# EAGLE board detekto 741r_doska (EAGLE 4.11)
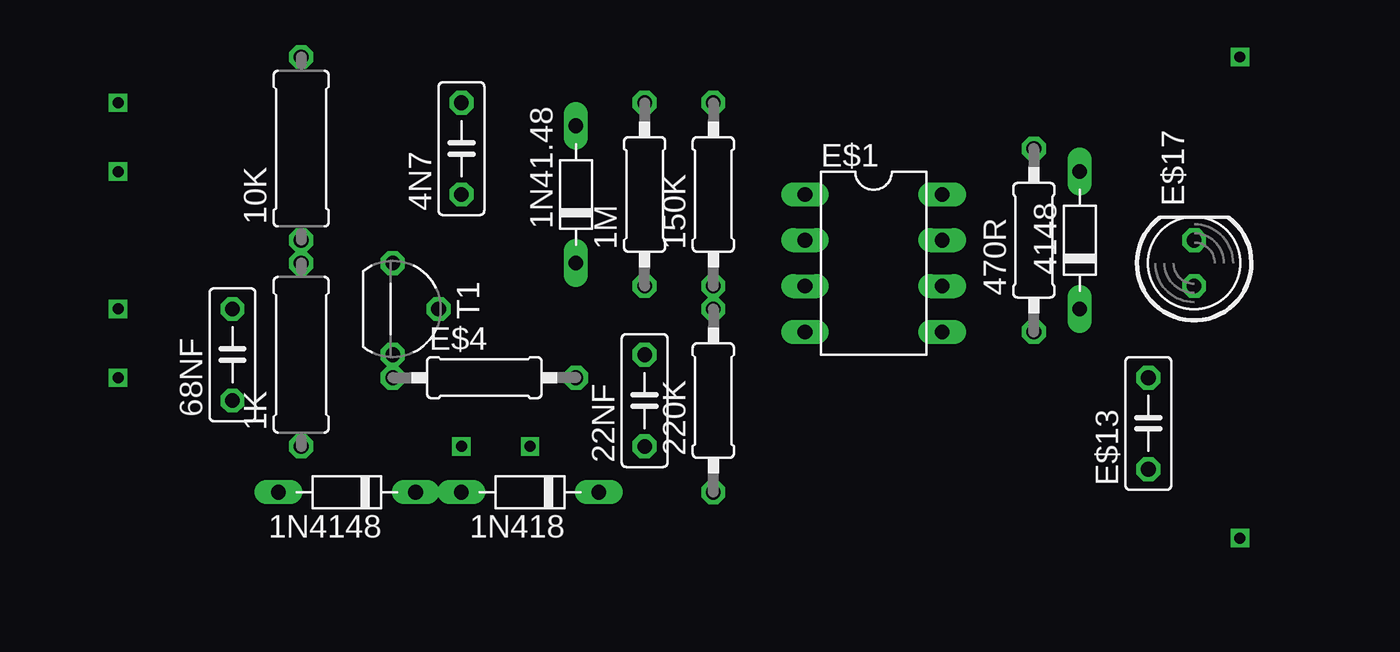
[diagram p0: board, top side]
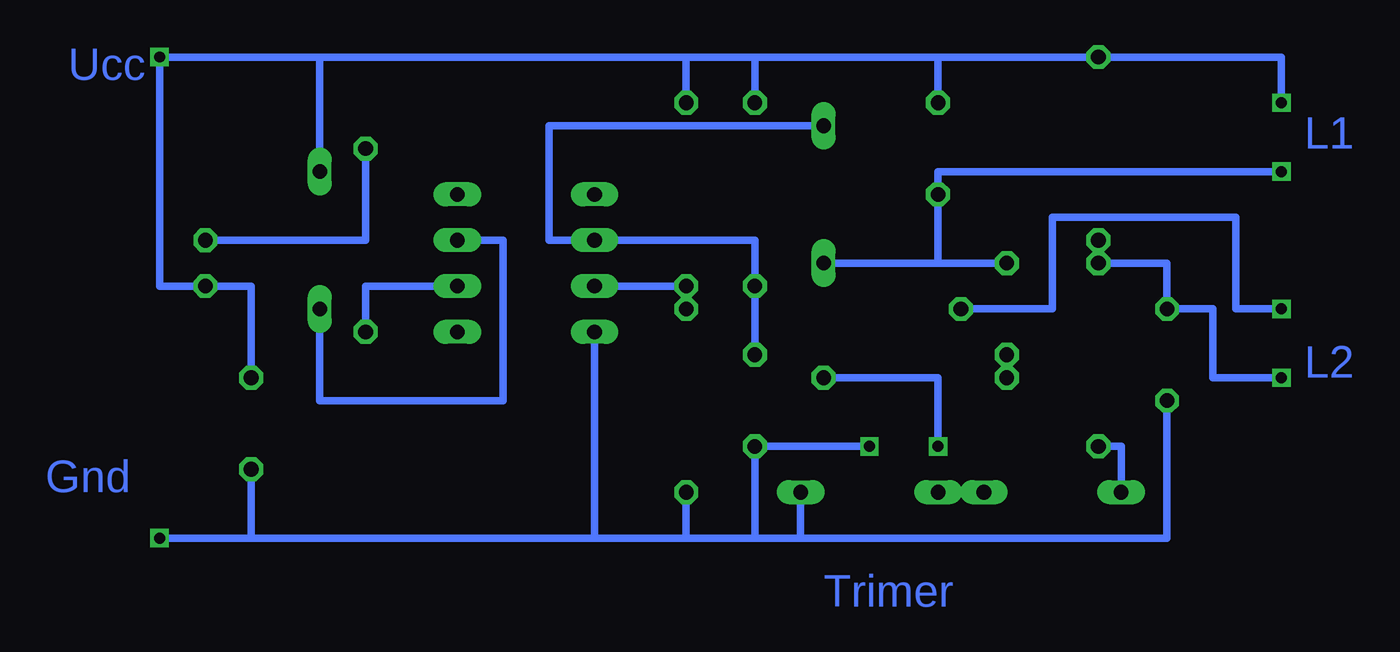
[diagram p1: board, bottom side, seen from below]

No outline drawn. Coordinates in mm, seen from the top.
Copper layers (1*16): Top 0.035mm / dielectric 1.5mm / Bottom 0.035mm
Design rules "default": minimum track width 10mil, minimum drill 24mil, track to track 8mil, track to pad 8mil, pad to pad 8mil, via to via 8mil, smd to smd 8mil, copper to edge 40mil, drill to drill 8mil, minimum pad ring 10mil, minimum via ring 8mil, stop-mask expansion 4mil, vias tented up to drill 0mil, thermal gap 10mil

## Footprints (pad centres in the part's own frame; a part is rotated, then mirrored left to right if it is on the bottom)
0309/10 = drill 0.813 octagon: 1 -5.08,0; 2 5.08,0
0207/10 = drill 0.813 octagon: 1 -5.08,0; 2 5.08,0
D-7.5 = drill 0.813 long: A 3.81,0; C -3.81,0
C050-025X075 = drill 0.813 octagon: 1 -2.54,0; 2 2.54,0
DIL08 = drill 0.813 long: 1 -3.81,-3.81; 2 -1.27,-3.81; 3 1.27,-3.81; 4 3.81,-3.81; 5 3.81,3.81; 6 1.27,3.81; 7 -1.27,3.81; 8 -3.81,3.81
LED5MM = drill 0.813 octagon: A -1.27,0; K 1.27,0
TO92L = drill 0.813 octagon: 1 2.54,0; 2 0,2.54; 3 -2.54,0

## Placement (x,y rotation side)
1K  [0309/10]  35.56,46.99 90 top
1M  [0207/10]  54.61,55.88 90 top
1N41.48  [D-7.5]  50.8,55.88 90 top
1N418  [D-7.5]  48.26,39.37 180 top
1N4148  [D-7.5]  38.1,39.37 180 top
4N7  [C050-025X075]  44.45,58.42 90 top
10K  [0309/10]  35.56,58.42 90 top
22NF  [C050-025X075]  54.61,44.45 90 top
68NF  [C050-025X075]  31.75,46.99 90 top
150K  [0207/10]  58.42,55.88 90 top
220K  [0207/10]  58.42,44.45 90 top
470R  [0207/10]  76.2,53.34 90 top
4148  [D-7.5]  78.74,53.34 90 top
E$1  [DIL08]  67.31,52.07 270 top
E$4  1k8  [0207/10]  45.72,45.72 0 top
E$13  [C050-025X075]  82.55,43.18 90 top
E$17  LED  [LED5MM]  85.09,52.07 90 top
T1  [TO92L]  40.64,49.53 270 top

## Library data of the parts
1K 1M 4N7 10K 22NF 68NF 150K 220K 470R E$4 E$13 = rcl
1N41.48 1N418 1N4148 4148 = diode
E$1 = 40xx
E$17 = led
T1 = transistor

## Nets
1!N4148: 470R.2 E$17.K
1K8: E$4.2
1N4148: 1N418.C 22NF.1 68NF.1 E$1.4 E$13.1
A: 1M.1 22NF.2 E$1.2
LED: 1M.2 4N7.2 150K.2 4148.A E$13.2 E$17.A
S$2: 1K.1 1N4148.A
S$3: 150K.1 220K.2
S$5: 4148.C E$1.7
S$7: T1.2
S$8: 470R.1
S$10: 1K.2 68NF.2
S$11: 1N41.48.C 4N7.1 T1.3

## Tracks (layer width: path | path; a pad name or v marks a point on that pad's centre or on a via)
1!N4148
  Bottom 0.406: 470R.2 76.2,53.34 E$17.K
1K8  (via drill 0.61)
  Bottom 0.406: E$4.2 44.45,45.72 v44.45,41.91
1N4148  (via drill 0.61)
  Bottom 0.406: 82.55,36.83 v87.63,36.83 | 82.55,36.83 E$13.1 | 63.5,36.83 82.55,36.83 | 63.5,36.83 E$1.4 | v48.26,41.91 22NF.1 54.61,36.83 | 58.42,36.83 58.42,39.37 | 58.42,36.83 63.5,36.83 | 54.61,36.83 58.42,36.83 | 68NF.1 31.75,36.83 52.07,36.83 | 52.07,36.83 54.61,36.83 | 1N418.C 52.07,36.83
A
  Bottom 0.406: 22NF.2 1M.1 54.61,53.34 E$1.2 66.04,53.34 66.04,59.69 50.8,59.69
LED  (via drill 0.61)
  Bottom 0.406: E$13.2 82.55,50.8 E$17.A 87.63,50.8 v87.63,63.5 78.74,63.5 | 54.61,63.5 1M.2 | 44.45,63.5 4N7.2 | 44.45,63.5 54.61,63.5 | 44.45,63.5 25.4,63.5 v25.4,60.96 | 54.61,63.5 58.42,63.5 | 58.42,63.5 78.74,63.5 | 150K.2 58.42,63.5 | 4148.A 78.74,63.5
S$2
  Bottom 0.406: 1N4148.A 34.29,41.91 1K.1
S$3
  Bottom 0.406: 220K.2 150K.1 62.23,50.8
S$5
  Bottom 0.406: E$1.7 68.58,53.34 68.58,44.45 78.74,44.45 4148.C
S$7  (via drill 0.61)
  Bottom 0.406: v25.4,49.53 27.94,49.53 27.94,54.61 38.1,54.61 38.1,49.53 T1.2
S$8
  Bottom 0.406: 72.39,50.8 76.2,50.8 470R.1
S$10  (via drill 0.61)
  Bottom 0.406: v25.4,45.72 29.21,45.72 29.21,49.53 68NF.2 31.75,52.07 1K.2
S$11  (via drill 0.61)
  Bottom 0.406: 44.45,52.07 4N7.1 44.45,57.15 v25.4,57.15 | T1.3 44.45,52.07 | 1N41.48.C 44.45,52.07

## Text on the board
Bottom: Ucc | L1 | L2 | Gnd | Trimer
